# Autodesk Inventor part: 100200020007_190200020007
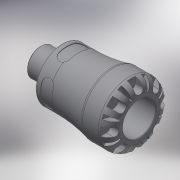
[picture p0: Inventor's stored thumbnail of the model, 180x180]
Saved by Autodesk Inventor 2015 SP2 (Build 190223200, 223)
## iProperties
Created: 2016-12
Part Number: 100200020007_190200020007
Material: Generic
Description: PLASSON MALE ADAPTOR 20X3/4" SERIES 1
Document SubType Name: Modeling
Designer: KIM
Mass: 447.839 g
Surface Area: 722.341 cm^2
Volume: 447.839 cm^3
Density: 1 g/cm^3
Appearance: Default
Author: KIM
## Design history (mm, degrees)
derived "1002.ipt"
feature "Solid1::1002.ipt"
tag "TaggingFeature1"
body "Solid1"
other parameters: "d0" = 71, "d1" = 18.9, "d3" = 25, "d4" = 41, "d6" = 45, "d8" = 34.85, "d13" = 6.4, "d14" = 6.4, "d15" = 0, "d17" = 360 deg, "d19" = 8 deg, "d20" = 0.4, "d21" = 0.4, "d22" = 8 deg, "d24" = 0, "d26" = 360 deg, "d32" = 0.925, "d33" = 4.1, "d34" = 26.441, "d35" = 2.5, "d38" = 17, "d39" = 0.79323, "d42" = 7, "d43" = 4.6, "d45" = 12.544, "d46" = 0, "d59" = 360 deg, "d61" = 5.95, "d62" = 0.4, "d64" = 0, "d65" = 0.41, "E_" = 41, "H_" = 71, "l_" = 45, "R_" = 26.441, "l_2" = 17, "d9" = 8, "d11" = 41, "d12" = 25
